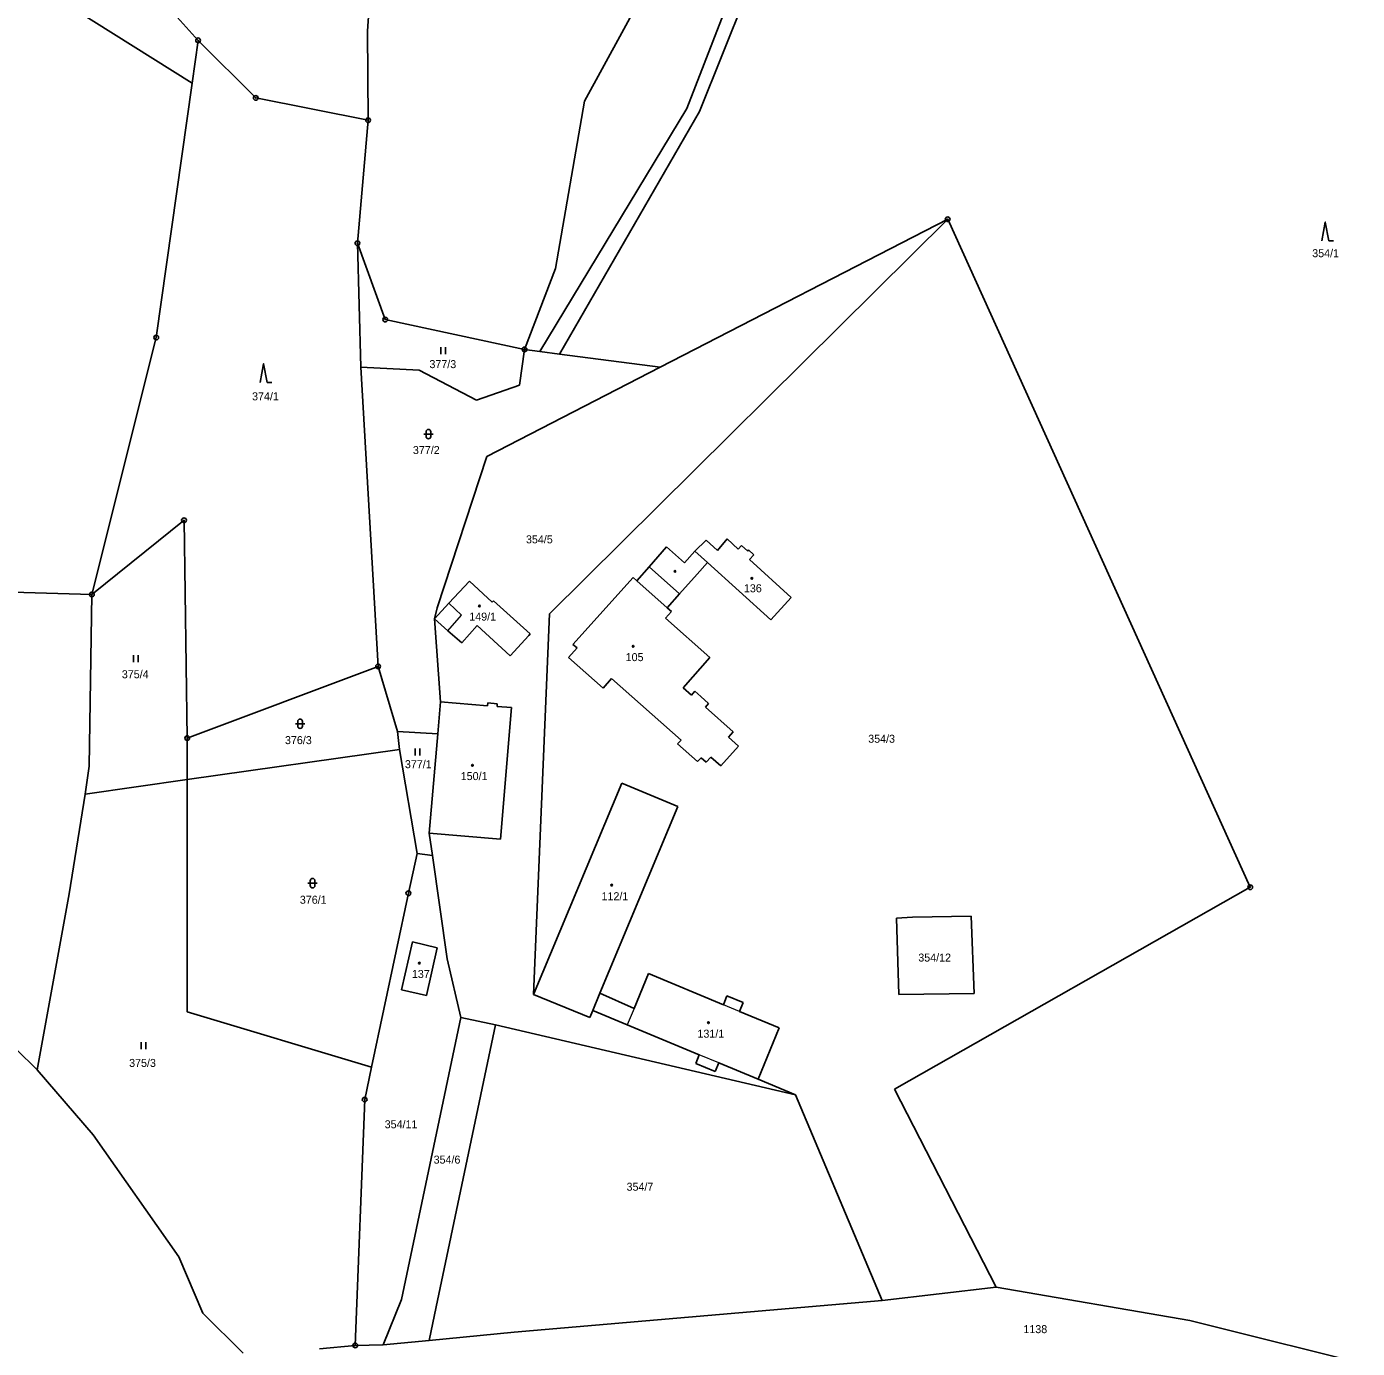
# Model space of a CAD drawing. Extents: x -765428 to -762163, y -1107632 to -1104975.
# Drawn here: x -764339.7 to -764056.9, y -1107160.9 to -1106880.1 of the extents above; entities that cross this region are included whole.
import ezdxf

# ---------------------------------------------------------------- set-up
doc = ezdxf.new("R2010")
doc.units = 0
doc.header["$LTSCALE"] = 0.68
for name, color, linetype, lineweight in [('1', 7, 'Continuous', 25), ('3', 7, 'Continuous', 25), ('4', 7, 'Continuous', 13), ('5', 7, 'Continuous', 25), ('8', 7, 'Continuous', 25)]:
    doc.layers.add(name, color=color, linetype=linetype, lineweight=lineweight)
doc.layers.add('2', color=7, linetype='Continuous')

msp = doc.modelspace()

# ---------------------------------------------------------------- linework, layer by layer
at = {"layer": '1'}
for p, q in [((-764420.5, -1106819.24), (-764304.49, -1106892.16)), ((-764266.15, -1106865.23), (-764267.24, -1106881.14)), ((-764203.18, -1106863.09), (-764221.14, -1106896.01)), ((-764199.42, -1106897.54), (-764186.42, -1106863.98)), ((-764196.71, -1106898.18), (-764183.21, -1106864.52)), ((-764303.23, -1106883.06), (-764314.41, -1106870.55)), ((-764267.24, -1106881.14), (-764267.13, -1106900.03)), ((-764303.23, -1106883.06), (-764304.49, -1106892.16)), ((-764303.23, -1106883.06), (-764290.99, -1106895.29)), ((-764304.49, -1106892.16), (-764312.14, -1106946.19)), ((-764267.13, -1106900.03), (-764290.99, -1106895.29)), ((-764221.14, -1106896.01), (-764227.33, -1106931.5)), ((-764199.42, -1106897.54), (-764230.65, -1106949.18)), ((-764226.46, -1106949.72), (-764196.71, -1106898.18)), ((-764269.4, -1106926.16), (-764267.13, -1106900.03)), ((-764228.57, -1107004.88), (-764143.99, -1106921.07)), ((-764205.08, -1106952.5), (-764143.99, -1106921.07)), ((-764143.99, -1106921.07), (-764079.71, -1107062.97)), ((-764268.7, -1106952.45), (-764269.4, -1106926.16)), ((-764269.4, -1106926.16), (-764263.48, -1106942.37)), ((-764227.33, -1106931.5), (-764233.88, -1106948.71)), ((-764263.48, -1106942.37), (-764233.88, -1106948.71)), ((-764312.14, -1106946.19), (-764325.8, -1107000.77)), ((-764234.97, -1106956.33), (-764233.88, -1106948.71)), ((-764233.88, -1106948.71), (-764230.65, -1106949.18)), ((-764230.65, -1106949.18), (-764226.46, -1106949.72)), ((-764226.46, -1106949.72), (-764205.08, -1106952.5)), ((-764264.99, -1107016.04), (-764268.7, -1106952.45)), ((-764268.7, -1106952.45), (-764256.29, -1106953.15)), ((-764256.29, -1106953.15), (-764244.07, -1106959.49)), ((-764205.08, -1106952.5), (-764241.92, -1106971.45)), ((-764244.07, -1106959.49), (-764234.97, -1106956.33)), ((-764241.92, -1106971.45), (-764252.47, -1107003.6)), ((-764325.8, -1107000.77), (-764306.23, -1106985)), ((-764306.23, -1106985), (-764305.56, -1107031.28)), ((-764197.71, -1106991.59), (-764195.3, -1106989.21)), ((-764195.3, -1106989.21), (-764192.88, -1106991.41)), ((-764192.88, -1106991.41), (-764190.85, -1106988.98)), ((-764190.85, -1106988.98), (-764188.52, -1106991.11)), ((-764207.42, -1106994.88), (-764203.7, -1106990.68)), ((-764203.7, -1106990.68), (-764199.9, -1106994.06)), ((-764199.9, -1106994.06), (-764197.71, -1106991.59)), ((-764195.01, -1106994), (-764197.71, -1106991.59)), ((-764188.52, -1106991.11), (-764187.81, -1106990.33)), ((-764187.81, -1106990.33), (-764186.47, -1106991.55)), ((-764186.47, -1106991.55), (-764186.27, -1106991.32)), ((-764186.27, -1106991.32), (-764185.16, -1106992.34)), ((-764185.16, -1106992.34), (-764186.07, -1106993.34)), ((-764210.05, -1106997.84), (-764207.42, -1106994.88)), ((-764195.01, -1106994), (-764197.21, -1106996.44)), ((-764181.57, -1107006.16), (-764195.01, -1106994)), ((-764186.07, -1106993.34), (-764177.25, -1107001.4)), ((-764249.95, -1107002.62), (-764245.6, -1106997.97)), ((-764245.6, -1106997.97), (-764240.78, -1107002.4)), ((-764223.59, -1107011.36), (-764210.82, -1106997.18)), ((-764210.82, -1106997.18), (-764210.05, -1106997.84)), ((-764197.21, -1106996.44), (-764200.94, -1107000.64)), ((-764325.8, -1107000.77), (-764342.65, -1107000.26)), ((-764326.36, -1107037.21), (-764325.8, -1107000.77)), ((-764200.94, -1107000.64), (-764203.57, -1107003.6)), ((-764253.03, -1107005.97), (-764249.95, -1107002.62)), ((-764252.47, -1107003.6), (-764253.03, -1107005.97)), ((-764240.78, -1107002.4), (-764240.48, -1107002.09)), ((-764240.48, -1107002.09), (-764232.67, -1107009.11)), ((-764203.57, -1107003.6), (-764202.67, -1107004.4)), ((-764177.25, -1107001.4), (-764181.57, -1107006.16)), ((-764251.76, -1107023.59), (-764253.03, -1107005.97)), ((-764250.2, -1107008.46), (-764253.03, -1107005.97)), ((-764231.99, -1107085.77), (-764228.57, -1107004.88)), ((-764202.67, -1107004.4), (-764203.93, -1107005.82)), ((-764203.93, -1107005.82), (-764194.49, -1107014.18)), ((-764247.21, -1107011.07), (-764250.2, -1107008.46)), ((-764243.94, -1107007.39), (-764247.21, -1107011.07)), ((-764236.96, -1107013.82), (-764243.94, -1107007.39)), ((-764232.98, -1107009.5), (-764236.96, -1107013.82)), ((-764232.67, -1107009.11), (-764232.98, -1107009.5)), ((-764222.73, -1107012.12), (-764224.52, -1107014.15)), ((-764223.59, -1107011.36), (-764222.73, -1107012.12)), ((-764224.52, -1107014.15), (-764217.21, -1107020.68)), ((-764194.49, -1107014.18), (-764200.16, -1107020.57)), ((-764305.56, -1107031.28), (-764264.99, -1107016.04)), ((-764264.99, -1107016.04), (-764260.87, -1107029.89)), ((-764217.21, -1107020.68), (-764215.39, -1107018.62)), ((-764215.39, -1107018.62), (-764200.64, -1107031.68)), ((-764200.16, -1107020.57), (-764198.4, -1107022.13)), ((-764252.34, -1107030.39), (-764251.76, -1107023.59)), ((-764251.76, -1107023.59), (-764241.74, -1107024.39)), ((-764241.74, -1107024.39), (-764241.7, -1107023.81)), ((-764241.7, -1107023.81), (-764239.67, -1107023.97)), ((-764198.4, -1107022.13), (-764197.7, -1107021.34)), ((-764197.7, -1107021.34), (-764196.43, -1107022.47)), ((-764196.43, -1107022.47), (-764194.78, -1107023.93)), ((-764239.67, -1107023.97), (-764239.69, -1107024.54)), ((-764239.69, -1107024.54), (-764236.67, -1107024.8)), ((-764236.67, -1107024.8), (-764239.02, -1107052.74)), ((-764194.78, -1107023.93), (-764195.47, -1107024.72)), ((-764195.47, -1107024.72), (-764189.56, -1107029.96)), ((-764305.56, -1107040.1), (-764305.56, -1107031.28)), ((-764260.87, -1107029.89), (-764252.34, -1107030.39)), ((-764260.43, -1107033.7), (-764260.87, -1107029.89)), ((-764254.13, -1107051.5), (-764252.34, -1107030.39)), ((-764200.64, -1107031.68), (-764201.37, -1107032.5)), ((-764189.56, -1107029.96), (-764190.58, -1107031.1)), ((-764190.58, -1107031.1), (-764188.45, -1107032.99)), ((-764260.43, -1107033.7), (-764305.56, -1107040.1)), ((-764256.73, -1107055.76), (-764260.43, -1107033.7)), ((-764201.37, -1107032.5), (-764197.11, -1107036.28)), ((-764188.45, -1107032.99), (-764192.16, -1107037.18)), ((-764327.2, -1107043.17), (-764326.36, -1107037.21)), ((-764197.11, -1107036.28), (-764196.38, -1107035.46)), ((-764196.38, -1107035.46), (-764195.29, -1107036.42)), ((-764194.3, -1107035.3), (-764195.29, -1107036.42)), ((-764192.16, -1107037.18), (-764194.3, -1107035.3)), ((-764305.56, -1107040.1), (-764327.2, -1107043.17)), ((-764305.54, -1107089.42), (-764305.56, -1107040.1)), ((-764327.2, -1107043.17), (-764330.64, -1107064.37)), ((-764231.99, -1107085.77), (-764213.22, -1107040.84)), ((-764213.22, -1107040.84), (-764201.34, -1107045.79)), ((-764201.34, -1107045.79), (-764217.86, -1107085.46)), ((-764254.13, -1107051.5), (-764253.46, -1107056.2)), ((-764239.02, -1107052.74), (-764254.13, -1107051.5)), ((-764258.57, -1107064.22), (-764256.73, -1107055.76)), ((-764256.73, -1107055.76), (-764253.46, -1107056.2)), ((-764253.46, -1107056.2), (-764250.33, -1107078.19)), ((-764079.71, -1107062.97), (-764155.29, -1107105.82)), ((-764330.64, -1107064.37), (-764337.42, -1107101.76)), ((-764266.4, -1107101.21), (-764258.57, -1107064.22)), ((-764139.01, -1107069.07), (-764151.45, -1107069.33)), ((-764138.34, -1107085.55), (-764139.01, -1107069.07)), ((-764151.45, -1107069.33), (-764154.85, -1107069.51)), ((-764154.85, -1107069.51), (-764154.34, -1107085.72)), ((-764260.03, -1107084.72), (-764257.71, -1107074.55)), ((-764257.71, -1107074.55), (-764252.42, -1107075.84)), ((-764252.42, -1107075.84), (-764254.7, -1107085.94)), ((-764250.33, -1107078.19), (-764247.42, -1107090.64)), ((-764210.6, -1107088.68), (-764207.55, -1107081.3)), ((-764207.55, -1107081.3), (-764191.65, -1107087.9)), ((-764254.7, -1107085.94), (-764260.03, -1107084.72)), ((-764220.02, -1107090.66), (-764231.99, -1107085.77)), ((-764217.86, -1107085.46), (-764219.39, -1107089.15)), ((-764217.86, -1107085.46), (-764210.6, -1107088.68)), ((-764191.65, -1107087.9), (-764190.88, -1107086.03)), ((-764190.88, -1107086.03), (-764187.46, -1107087.45)), ((-764154.34, -1107085.72), (-764138.34, -1107085.55)), ((-764187.46, -1107087.45), (-764188.24, -1107089.32)), ((-764266.4, -1107101.21), (-764305.54, -1107089.42)), ((-764247.42, -1107090.64), (-764259.99, -1107150.55)), ((-764240.07, -1107092.19), (-764247.42, -1107090.64)), ((-764219.39, -1107089.15), (-764220.02, -1107090.66)), ((-764212.06, -1107092.19), (-764219.39, -1107089.15)), ((-764188.24, -1107089.32), (-764179.76, -1107092.83)), ((-764252.66, -1107152.09), (-764240.07, -1107092.19)), ((-764176.32, -1107107.03), (-764240.07, -1107092.19)), ((-764196.75, -1107098.54), (-764212.06, -1107092.19)), ((-764179.76, -1107092.83), (-764184.28, -1107103.72)), ((-764341.92, -1107097.33), (-764337.42, -1107101.76)), ((-764197.52, -1107100.39), (-764196.75, -1107098.54)), ((-764337.42, -1107101.76), (-764325.5, -1107115.56)), ((-764267.85, -1107108.07), (-764266.4, -1107101.21)), ((-764193.36, -1107102.11), (-764197.52, -1107100.39)), ((-764192.6, -1107100.26), (-764193.36, -1107102.11)), ((-764184.28, -1107103.72), (-764192.6, -1107100.26)), ((-764184.28, -1107103.72), (-764176.32, -1107107.03)), ((-764155.29, -1107105.82), (-764133.71, -1107147.88)), ((-764269.84, -1107160.28), (-764267.85, -1107108.07)), ((-764157.92, -1107150.73), (-764176.32, -1107107.03)), ((-764325.5, -1107115.56), (-764307.3, -1107141.45)), ((-764307.3, -1107141.45), (-764302.2, -1107153.46)), ((-764157.92, -1107150.73), (-764133.71, -1107147.88)), ((-764133.71, -1107147.88), (-764092.57, -1107154.99)), ((-764259.99, -1107150.55), (-764263.95, -1107160.17)), ((-764236.09, -1107157.5), (-764157.92, -1107150.73)), ((-764302.2, -1107153.46), (-764293.68, -1107161.91)), ((-764254.16, -1107159.23), (-764252.66, -1107152.09)), ((-764092.57, -1107154.99), (-764025.72, -1107171.67)), ((-764263.95, -1107160.17), (-764254.16, -1107159.23)), ((-764254.16, -1107159.23), (-764236.09, -1107157.5)), ((-764269.84, -1107160.28), (-764277.42, -1107161.04)), ((-764263.95, -1107160.17), (-764269.84, -1107160.28))]:
    msp.add_line(p, q, dxfattribs=at)
at = {"layer": '3'}
for p, q in [((-764063.02, -1106925.66), (-764062.024, -1106925.66)), ((-764251.661, -1106949.71), (-764251.661, -1106948.21)), ((-764250.66, -1106949.71), (-764250.66, -1106948.21)), ((-764288.57, -1106955.76), (-764287.574, -1106955.76)), ((-764255.311, -1106966.701), (-764253.309, -1106966.701)), ((-764254.811, -1106966.201), (-764254.811, -1106967.202)), ((-764253.809, -1106967.202), (-764253.809, -1106966.201)), ((-764316.981, -1107015.15), (-764316.981, -1107013.65)), ((-764315.98, -1107015.15), (-764315.98, -1107013.65)), ((-764282.571, -1107028.231), (-764280.569, -1107028.231)), ((-764282.071, -1107027.731), (-764282.071, -1107028.732)), ((-764281.069, -1107028.732), (-764281.069, -1107027.731)), ((-764257.121, -1107034.99), (-764257.121, -1107033.49)), ((-764256.12, -1107034.99), (-764256.12, -1107033.49)), ((-764279.931, -1107062.091), (-764277.929, -1107062.091)), ((-764279.431, -1107061.591), (-764279.431, -1107062.592)), ((-764278.429, -1107062.592), (-764278.429, -1107061.591)), ((-764315.341, -1107097.33), (-764315.341, -1107095.83)), ((-764314.34, -1107097.33), (-764314.34, -1107095.83))]:
    msp.add_line(p, q, dxfattribs=at)
for points in [[(-764063.02, -1106925.66), (-764063.77, -1106921.66), (-764064.52, -1106925.66)], [(-764288.57, -1106955.76), (-764289.32, -1106951.76), (-764290.07, -1106955.76)]]:
    msp.add_lwpolyline(points, dxfattribs=at)
for centre, start, end in [((-764254.31, -1106966.2009), 0, 180), ((-764254.31, -1106967.2009), 180, 359.98789), ((-764281.57, -1107027.7309), 0, 180), ((-764281.57, -1107028.7309), 180, 359.98789), ((-764278.93, -1107061.5909), 0, 180), ((-764278.93, -1107062.5909), 180, 359.98789)]:
    msp.add_arc(centre, 0.5, start, end, dxfattribs=at)
at = {"layer": '4'}
for p, q in [((-764200.94, -1107000.64), (-764207.42, -1106994.88)), ((-764210.05, -1106997.84), (-764203.57, -1107003.6)), ((-764247.25, -1107005.17), (-764249.95, -1107002.62)), ((-764250.2, -1107008.46), (-764247.25, -1107005.17)), ((-764210.6, -1107088.68), (-764212.06, -1107092.19)), ((-764188.24, -1107089.32), (-764191.65, -1107087.9)), ((-764192.6, -1107100.26), (-764196.75, -1107098.54))]:
    msp.add_line(p, q, dxfattribs=at)
at = {"layer": '5'}
for centre in [(-764201.9268, -1106995.8392), (-764185.5868, -1106997.3392), (-764243.4668, -1107003.1992), (-764210.8068, -1107011.7792), (-764244.9468, -1107037.0492), (-764215.3768, -1107062.5092), (-764256.2468, -1107079.0692), (-764194.8168, -1107091.7292)]:
    msp.add_circle(centre, 0.175, dxfattribs=at)
at = {"layer": '8'}
for centre, radius in [((-764303.23, -1106883.0599), 0.5), ((-764303.23, -1106883.0599), 0.0303), ((-764290.99, -1106895.2899), 0.5), ((-764290.99, -1106895.2899), 0.0303), ((-764267.13, -1106900.0299), 0.5), ((-764267.13, -1106900.0299), 0.0303), ((-764143.99, -1106921.0699), 0.5), ((-764143.99, -1106921.0699), 0.0303), ((-764269.4, -1106926.1599), 0.5), ((-764269.4, -1106926.1599), 0.0303), ((-764263.48, -1106942.3699), 0.5), ((-764263.48, -1106942.3699), 0.0303), ((-764312.14, -1106946.1899), 0.5), ((-764312.14, -1106946.1899), 0.0303), ((-764233.88, -1106948.7099), 0.5), ((-764233.88, -1106948.7099), 0.0303), ((-764306.23, -1106984.9999), 0.5), ((-764306.23, -1106984.9999), 0.0303), ((-764325.8, -1107000.7699), 0.5), ((-764325.8, -1107000.7699), 0.0303), ((-764264.99, -1107016.0399), 0.5), ((-764264.99, -1107016.0399), 0.0303), ((-764305.56, -1107031.2799), 0.5), ((-764305.56, -1107031.2799), 0.0303), ((-764079.71, -1107062.9699), 0.5), ((-764079.71, -1107062.9699), 0.0303), ((-764258.57, -1107064.2199), 0.5), ((-764258.57, -1107064.2199), 0.0303), ((-764267.85, -1107108.0699), 0.5), ((-764267.85, -1107108.0699), 0.0303), ((-764269.84, -1107160.2799), 0.5), ((-764269.84, -1107160.2799), 0.0303)]:
    msp.add_circle(centre, radius, dxfattribs=at)

# ---------------------------------------------------------------- texts
at = {"layer": '2'}
for s, p in [('354/1', (-764066.54, -1106929.125)), ('377/3', (-764254.09, -1106952.685)), ('374/1', (-764291.77, -1106959.525)), ('377/2', (-764257.6, -1106970.935)), ('354/5', (-764233.58, -1106989.905)), ('136', (-764187.28, -1107000.305)), ('149/1', (-764245.63, -1107006.325)), ('105', (-764212.4, -1107014.925)), ('375/4', (-764319.44, -1107018.565)), ('376/3', (-764284.78, -1107032.555)), ('354/3', (-764160.87, -1107032.265)), ('377/1', (-764259.3, -1107037.665)), ('150/1', (-764247.44, -1107040.195)), ('376/1', (-764281.62, -1107066.465)), ('112/1', (-764217.53, -1107065.715)), ('354/12', (-764150.23, -1107078.745)), ('137', (-764257.82, -1107082.235)), ('131/1', (-764197.15, -1107094.915)), ('375/3', (-764317.89, -1107101.125)), ('354/11', (-764263.6, -1107114.155)), ('354/6', (-764253.2, -1107121.665)), ('354/7', (-764212.21, -1107127.425)), ('1138', (-764127.9, -1107157.675))]:
    msp.add_text(s, height=1.7, dxfattribs=at).set_placement(p)

doc.saveas('drawing.dxf')
